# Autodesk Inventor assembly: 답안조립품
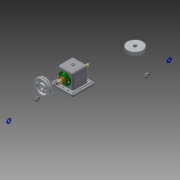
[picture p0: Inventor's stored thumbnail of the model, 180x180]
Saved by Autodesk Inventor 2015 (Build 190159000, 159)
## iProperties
Created: 2018-11
Part Number: 답안조립품
Document SubType Name: Assembly
Designer: now333
Author: now333
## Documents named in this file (13)
- C:\Users\now333\Desktop\481108V1011\답안조립품.iam
- C:\Users\now333\Desktop\481108V1011\V벨트풀리.ipt
- C:\Users\now333\Desktop\481108V1011\너트 M12x1.25.ipt
- C:\Users\now333\Desktop\481108V1011\베어링 6203.ipt
- C:\Users\now333\Desktop\481108V1011\본체.ipt
- C:\Users\now333\Desktop\481108V1011\볼트 M4.ipt
- C:\Users\now333\Desktop\481108V1011\부시.ipt
- C:\Users\now333\Desktop\481108V1011\스퍼기어.ipt
- C:\Users\now333\Desktop\481108V1011\오일 실 26 38 8.ipt
- C:\Users\now333\Desktop\481108V1011\와셔 12x24.ipt
- C:\Users\now333\Desktop\481108V1011\축.ipt
- C:\Users\now333\Desktop\481108V1011\커버.ipt
- C:\Users\now333\Desktop\481108V1011\키 5x5x12.ipt
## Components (1 placed, 1 different names)
1. V벨트풀리:1
